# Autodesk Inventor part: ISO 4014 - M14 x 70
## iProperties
IsCustomPart: 0
Created: 2009-02
Part Number: ISO 4014 - M14 x 70
Material: Stainless Steel, 440C
Description: Hexagon head bolt - product grades A and B
Document SubType Name: Modeling
Standard: ISO 4014
Designer: 904Chiaki
Standard Revision: Third edition 1999-09-01
Standards Organization: ISO
Language: en-US
Size Designation: M14 x 70
Categories: <MemberInstance><Categories><Category DisplayName="Fasteners" InternalName="e4da775c-781d-43d5-af7c-5136215cf5a6" Mnemonic="FSTN"><Category DisplayName="Bolts"
Density: 7.75 g/cm^3
Mass: 108.833 g
Surface Area: 44.2416 cm^2
Volume: 14.043 cm^3
Author: 904Chiaki
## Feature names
1. Body [Revolution]
2. Head [Extrusion]
3. Chamfer1 [Revolution]
4. Chamfer2
